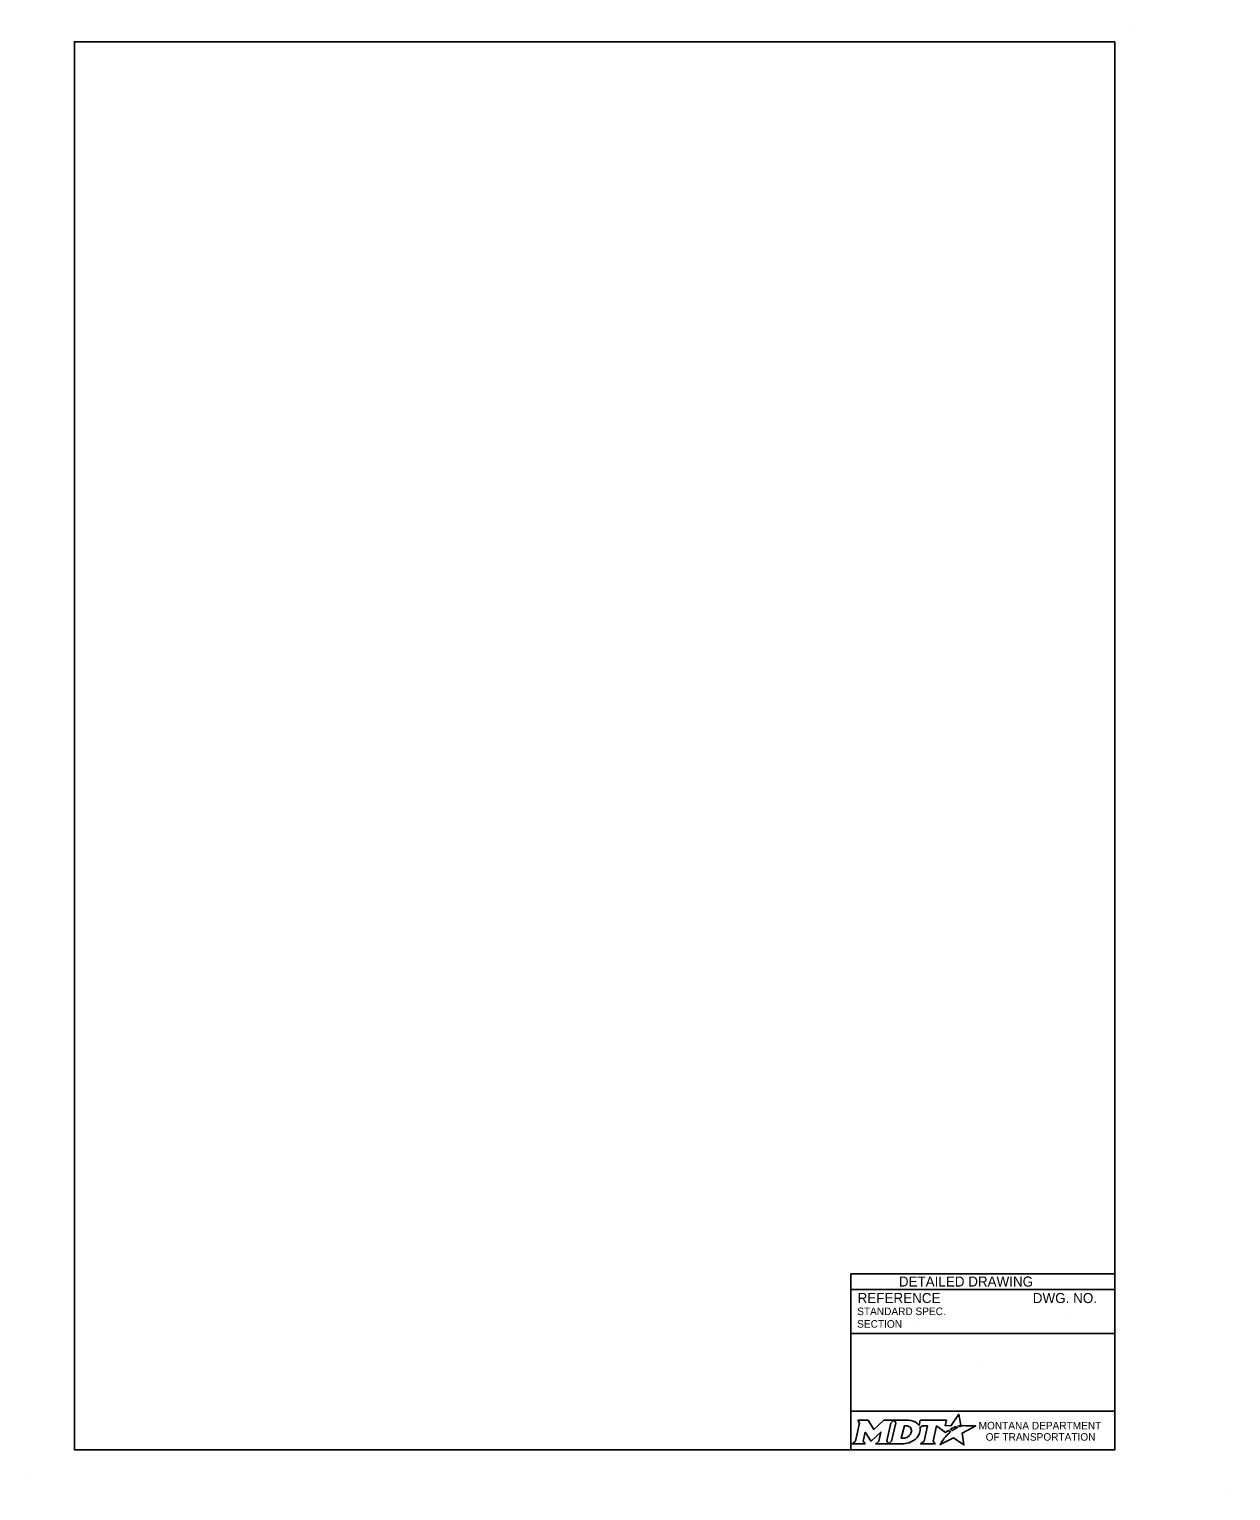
# Model space of a CAD drawing. Extents: x 49977.1 to 50021, y 49987.6 to 50011.4.
# Drawn here: x 49999.98 to 50009.54, y 49999.74 to 50011.36 of the extents above; entities that cross this region are included whole.
import ezdxf

# ---------------------------------------------------------------- set-up
doc = ezdxf.new("R2010")
doc.units = 0
doc.layers.add('Level 1', color=7, linetype='Continuous')
doc.layers.add('Level 2', color=7, linetype='Continuous')

msp = doc.modelspace()

# ---------------------------------------------------------------- linework, layer by layer
at = {"layer": 'Level 1'}
for p, q in [((50008.765, 50011.363), (50008.765, 50011.363)), ((49999.977, 49999.862), (49999.977, 49999.862)), ((50009.537, 49999.736), (50009.537, 49999.736))]:
    msp.add_line(p, q, dxfattribs=at)
msp.add_lwpolyline([(50008.615, 50011.263), (50000.336, 50011.263), (50000.336, 50000.062), (50008.615, 50000.062)], close=True, dxfattribs=at)
at = {"layer": 'Level 2'}
for p, q in [((50008.615, 50001.462), (50006.515, 50001.462)), ((50006.515, 50001.462), (50006.515, 50000.062)), ((50008.615, 50001.337), (50006.515, 50001.337)), ((50007.009, 50001.063), (50007.009, 50001.063)), ((50008.251, 50001.122), (50008.251, 50001.122)), ((50008.615, 50000.987), (50006.515, 50000.987)), ((50007.565, 50000.738), (50007.565, 50000.738)), ((50008.615, 50000.369), (50006.515, 50000.369))]:
    msp.add_line(p, q, dxfattribs=at)
for points in [[(50007.377, 50000.245), (50007.367, 50000.25), (50007.378, 50000.253), (50007.39, 50000.255), (50007.373, 50000.345), (50007.313, 50000.254), (50007.266, 50000.253), (50007.276, 50000.297), (50007.067, 50000.297), (50007.057, 50000.255), (50007.051, 50000.263)], [(50006.57, 50000.297), (50006.584, 50000.274), (50006.551, 50000.131), (50006.525, 50000.108), (50006.627, 50000.108), (50006.613, 50000.131), (50006.629, 50000.201), (50006.673, 50000.132), (50006.678, 50000.132), (50006.753, 50000.202), (50006.737, 50000.13), (50006.712, 50000.108), (50006.814, 50000.108), (50006.8, 50000.132), (50006.833, 50000.274)], [(50006.833, 50000.274), (50006.859, 50000.297), (50006.776, 50000.297), (50006.697, 50000.224), (50006.652, 50000.297), (50006.57, 50000.297)], [(50006.972, 50000.297), (50006.859, 50000.297), (50006.873, 50000.275), (50006.839, 50000.131), (50006.814, 50000.108), (50006.925, 50000.108)], [(50006.996, 50000.211), (50006.995, 50000.203), (50006.992, 50000.193), (50006.988, 50000.185), (50006.982, 50000.178), (50006.976, 50000.171), (50006.968, 50000.164), (50006.959, 50000.16), (50006.95, 50000.156), (50006.941, 50000.154), (50006.932, 50000.153), (50006.916, 50000.153), (50006.94, 50000.253), (50006.956, 50000.253), (50006.963, 50000.252), (50006.971, 50000.25), (50006.977, 50000.247), (50006.983, 50000.243), (50006.988, 50000.238), (50006.992, 50000.232), (50006.995, 50000.226), (50006.996, 50000.218), (50006.996, 50000.215), (50006.996, 50000.211)], [(50007.064, 50000.238), (50007.088, 50000.251), (50007.125, 50000.251), (50007.097, 50000.131), (50007.069, 50000.108), (50007.185, 50000.108), (50007.168, 50000.131), (50007.196, 50000.251), (50007.268, 50000.2), (50007.289, 50000.215), (50007.309, 50000.204)], [(50007.253, 50000.148), (50007.237, 50000.124), (50007.233, 50000.116), (50007.227, 50000.107), (50007.225, 50000.103), (50007.33, 50000.156), (50007.414, 50000.101), (50007.401, 50000.194), (50007.508, 50000.252), (50007.458, 50000.253), (50007.428, 50000.253), (50007.407, 50000.254), (50007.401, 50000.252), (50007.396, 50000.251), (50007.387, 50000.249), (50007.377, 50000.245)], [(50007.327, 50000.217), (50007.324, 50000.215), (50007.306, 50000.225), (50007.316, 50000.231), (50007.32, 50000.233), (50007.329, 50000.237), (50007.335, 50000.239), (50007.343, 50000.243), (50007.35, 50000.245), (50007.362, 50000.238), (50007.358, 50000.236), (50007.353, 50000.233), (50007.349, 50000.231), (50007.344, 50000.228), (50007.342, 50000.227), (50007.339, 50000.225), (50007.337, 50000.224), (50007.334, 50000.222), (50007.332, 50000.221), (50007.329, 50000.219), (50007.327, 50000.217)], [(50006.97, 50000.116), (50006.979, 50000.118), (50006.992, 50000.124), (50007.012, 50000.135)], [(50007.267, 50000.164), (50007.267, 50000.164)]]:
    msp.add_lwpolyline(points, dxfattribs=at)
for centre, radius, start, end in [((50006.995, 50000.219), 0.0709, 339.5329, 15.8582), ((50006.951, 50000.236), 0.118, 300.9103, 339.1383)]:
    msp.add_arc(centre, radius, start, end, dxfattribs=at)
for centre, major_axis, ratio, start_param, end_param in [((50006.97, 50000.25), (0.0834, -0.0037), 0.568097, 0.61298, 1.570796), ((50007.026, 50000.257), (0.0361, -0.0295), 0.469099, 1.225588, 1.570796), ((50006.925, 50000.257), (0, 0.148), 0.987302, 3.139398, 3.456847), ((50007.26, 50000.156), (-0.00694, -0.00806), 0.008222, 0, 3.137361), ((50007.276, 50000.174), (-0.0098, -0.0102), 0.016458, 3.141593, 6.279097), ((50007.297, 50000.194), (-0.0112, -0.0097), 0.021651, 3.157348, 6.283185)]:
    msp.add_ellipse(centre, major_axis=major_axis, ratio=ratio, start_param=start_param, end_param=end_param, dxfattribs=at)

# ---------------------------------------------------------------- texts
for s, height, p in [('DETAILED DRAWING', 0.0799, (50006.896, 50001.36)), ('REFERENCE', 0.08, (50006.568, 50001.229)), ('DWG. NO.', 0.08, (50007.962, 50001.229)), ('STANDARD SPEC.', 0.06, (50006.565, 50001.133)), ('SECTION', 0.06, (50006.565, 50001.033)), ('MONTANA DEPARTMENT', 0.06, (50007.531, 50000.224)), ('OF TRANSPORTATION', 0.06, (50007.587, 50000.134))]:
    msp.add_text(s, height=height, dxfattribs=at).set_placement(p)

doc.saveas('drawing.dxf')
